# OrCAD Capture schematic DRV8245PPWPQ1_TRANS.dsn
size Custom; title: DRV8245-Q1 Automotive H-Bridge Driver with; rev: 1.0; note: Datasheet: SLVSFJ1A      EVM: NA; note: Synchronous Step Down Converter
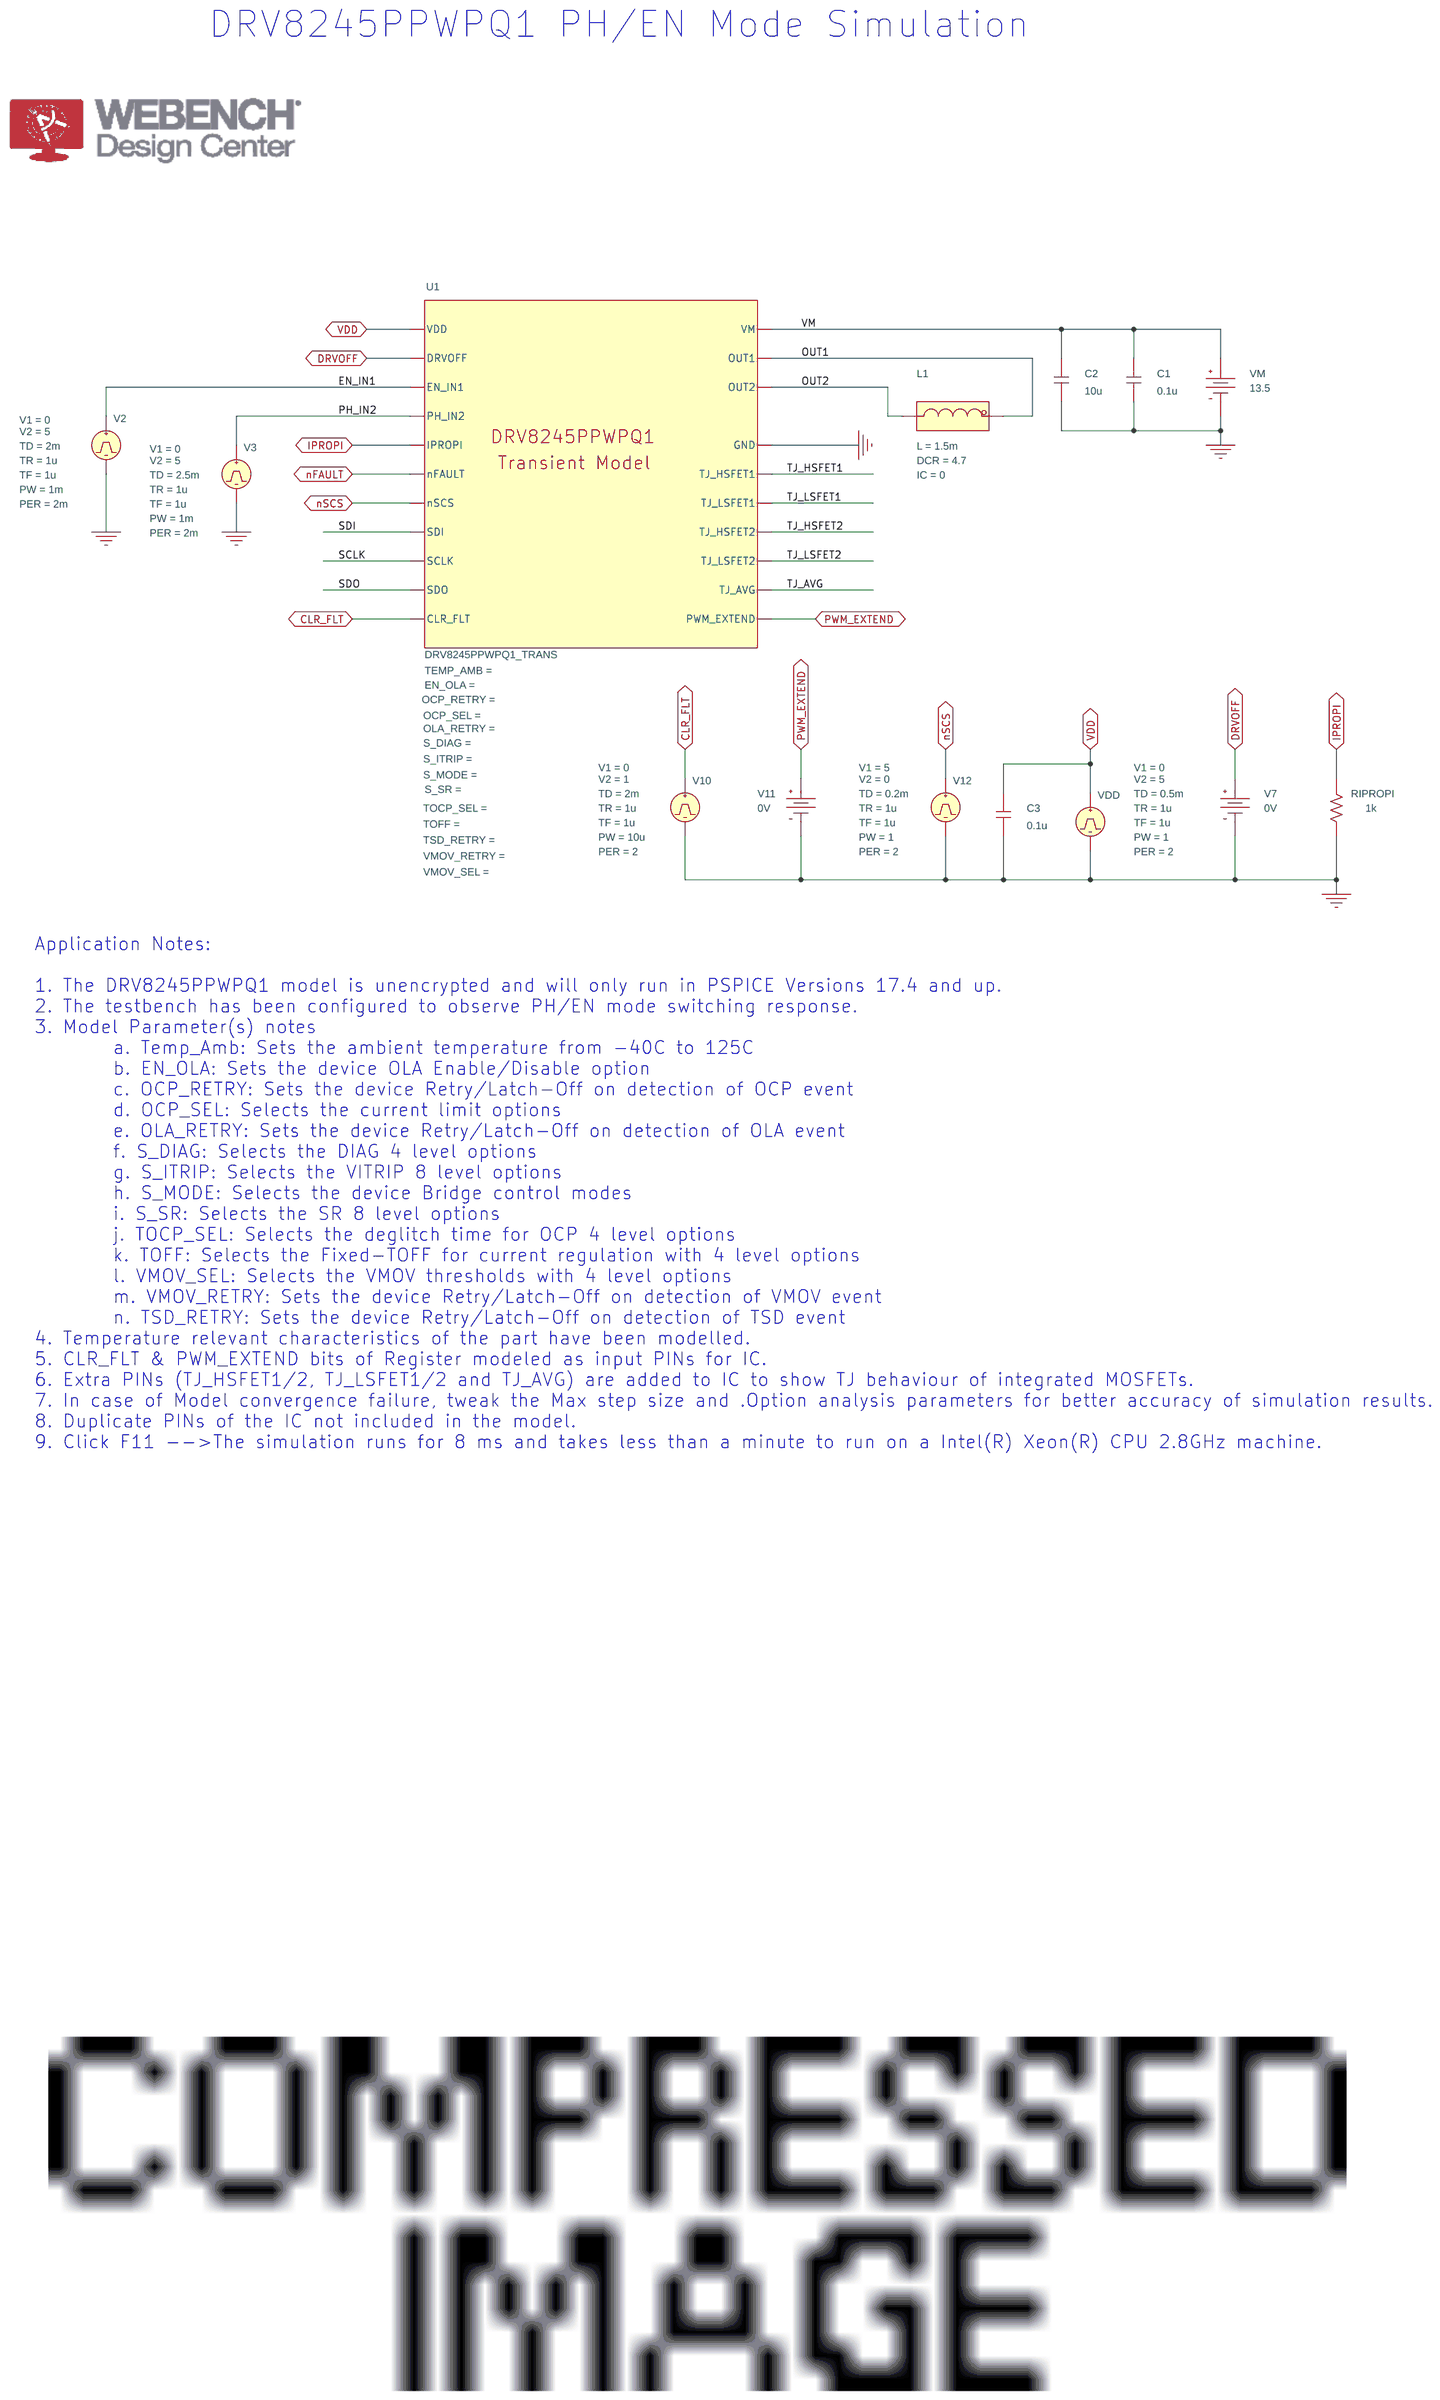
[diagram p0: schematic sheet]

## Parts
C1  0.1u  [RAD/CK05]
C2  10u  [RAD/CK05]
C3  0.1u  [RAD/CK05]
L1  LDCR
RIPROPI  1k  [AXRC05]
U1  DRV8245PPWPQ1_TRANS
V2  VPULSE
V3  VPULSE
V7  VDC
V10  VPULSE
V11  VDC
V12  VPULSE
VDD  VPULSE
VM  VDC

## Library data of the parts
C1-C3 = C
L1 = LDCR: DCR: 4.7; IC: 0; L: 1.5m; PSpiceTemplate: X^@REFDES %IN %OUT @MODEL PARAMS:  ?L|L=@L||L=1u|  ?DCR|DCR=@DCR||DCR=0.01| ?IC|IC=@IC||IC=0|
RIPROPI = R
U1 = DRV8245PPWPQ1_TRANS
V2 = VPULSE: PER: 2m; PW: 1m; TD: 2m; TF: 1u; TR: 1u; V1: 0; V2: 5
V3 = VPULSE: PER: 2m; PW: 1m; TD: 2.5m; TF: 1u; TR: 1u; V1: 0; V2: 5
V7 V11 = VDC: DC: 0V
V10 = VPULSE: PER: 2; PW: 10u; TD: 2m; TF: 1u; TR: 1u; V1: 0; V2: 1
V12 = VPULSE: PER: 2; PW: 1; TD: 0.2m; TF: 1u; TR: 1u; V1: 5; V2: 0
VDD = VPULSE: PER: 2; PW: 1; TD: 0.5m; TF: 1u; TR: 1u; V1: 0; V2: 5
VM = VDC: DC: 13.5

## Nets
VDD: C3.1 U1.VDD VDD.1(+)
0: C1.2 C2.2 C3.2 RIPROPI.2 U1.GND V2.2(-) V3.2(-) V7.1(-) V10.2(-) V11.1(-) V12.2(-) VDD.2(-) VM.1(-)
CLR_FLT: U1.CLR_FLT V10.1(+)
DRVOFF: U1.DRVOFF V7.0(+)
EN_IN1: U1.EN_IN1 V2.1(+)
IPROPI: RIPROPI.1 U1.IPROPI
nFAULT: U1.nFAULT
nSCS: U1.nSCS V12.1(+)
OUT1: L1.1(IN) U1.OUT1
OUT2: L1.3(OUT) U1.OUT2
PH_IN2: U1.PH_IN2 V3.1(+)
PWM_EXTEND: U1.PWM_EXTEND V11.0(+)
SCLK: U1.SCLK
SDI: U1.SDI
SDO: U1.SDO
TJ_AVG: U1.TJ_AVG
TJ_HSFET1: U1.TJ_HSFET1
TJ_HSFET2: U1.TJ_HSFET2
TJ_LSFET1: U1.TJ_LSFET1
TJ_LSFET2: U1.TJ_LSFET2
VM: C1.1 C2.1 U1.VM VM.0(+)

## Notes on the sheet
- DRV8245PPWPQ1 PH/EN Mode Simulation
- Application Notes:
  1. The DRV8245PPWPQ1 model is unencrypted and will only run in PSPICE Versions 17.4 and up.
  2. The testbench has been configured to observe PH/EN mode switching response.
  3. Model Parameter(s) notes
          a. Temp_Amb: Sets the ambient temperature from -40C to 125C
          b. EN_OLA: Sets the device OLA Enable/Disable option
          c. OCP_RETRY: Sets the device Retry/Latch-Off on detection of OCP event
          d. OCP_SEL: Selects the current limit options
          e. OLA_RETRY: Sets the device Retry/Latch-Off on detection of OLA event
          f. S_DIAG: Selects the DIAG 4 level options
          g. S_ITRIP: Selects the VITRIP 8 level options
          h. S_MODE: Selects the device Bridge control modes
          i. S_SR: Selects the SR 8 level options
          j. TOCP_SEL: Selects the deglitch time for OCP 4 level options
          k. TOFF: Selects the Fixed-TOFF for current regulation with 4 level options
          l. VMOV_SEL: Selects the VMOV thresholds with 4 level options
          m. VMOV_RETRY: Sets the device Retry/Latch-Off on detection of VMOV event
          n. TSD_RETRY: Sets the device Retry/Latch-Off on detection of TSD event
  4. Temperature relevant characteristics of the part have been modelled.
  5. CLR_FLT & PWM_EXTEND bits of Register modeled as input PINs for IC.
  6. Extra PINs (TJ_HSFET1/2, TJ_LSFET1/2 and TJ_AVG) are added to IC to show TJ behaviour of integrated MOSFETs.
  7. In case of Model convergence failure, tweak the Max step size and .Option analysis parameters for better accuracy of simulation results.
  8. Duplicate PINs of the IC not included in the model.
  9. Click F11 -->The simulation runs for 8 ms and takes less than a minute to run on a Intel(R) Xeon(R) CPU 2.8GHz machine.
